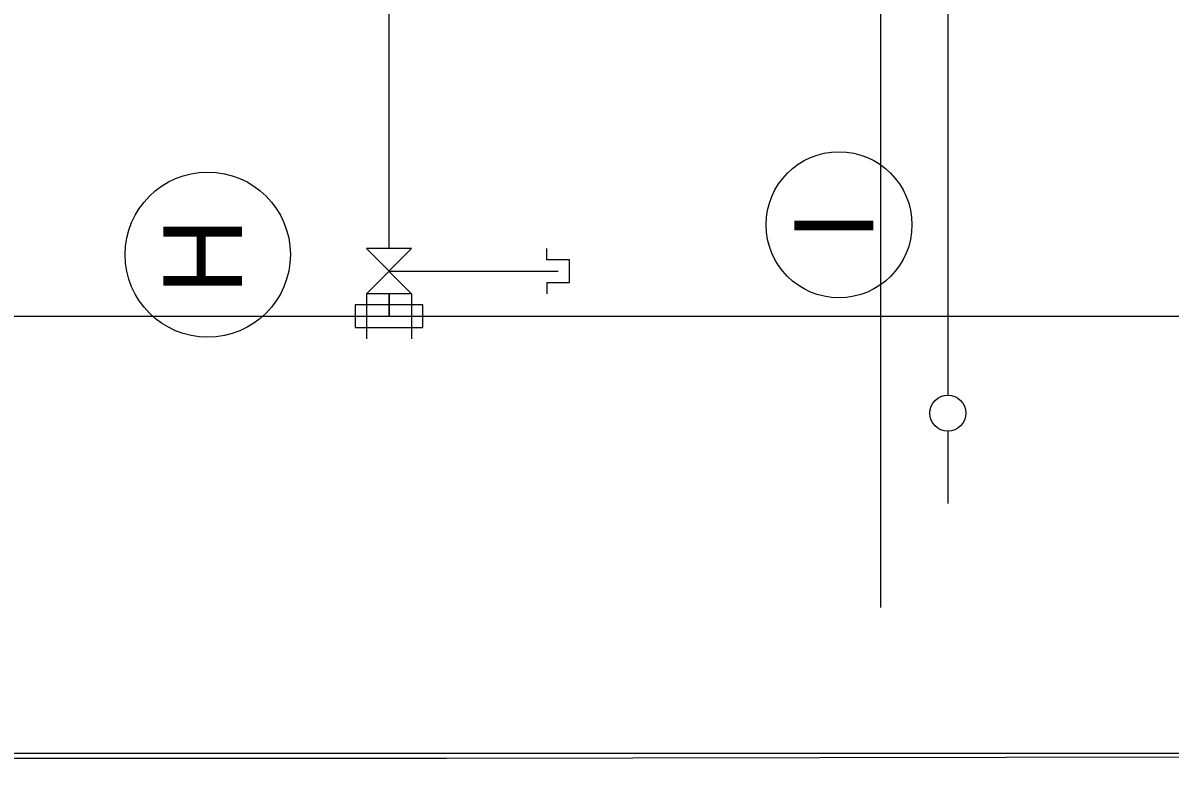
# Model space of a CAD drawing. Extents: x -264205 to -263659, y -1242401 to -1241986.
# Drawn here: x -263871.58 to -263858.86, y -1242255.16 to -1242246.89 of the extents above; entities that cross this region are included whole.
import ezdxf

# ---------------------------------------------------------------- set-up
doc = ezdxf.new("R2010")
doc.units = 0
for name, color, linetype in [('HESCON_OSI_STAVBY_KFA', 7, 'Continuous'), ('PROJEKT_OBRUBNIKY_KOMUNIKACIE', 7, 'Continuous'), ('SITUACIA_DSP_2D', 7, 'Continuous'), ('SO_20-2_OBRUBNIKY_HORNA_HRANA', 7, 'Continuous')]:
    doc.layers.add(name, color=color, linetype=linetype)

msp = doc.modelspace()

# ---------------------------------------------------------------- linework, layer by layer
at = {"layer": 'HESCON_OSI_STAVBY_KFA'}
for centre, radius in [((-263862.528, -1242249.126), 0.809), ((-263869.528, -1242249.457), 0.916)]:
    msp.add_circle(centre, radius, dxfattribs=at)
at = {"layer": 'PROJEKT_OBRUBNIKY_KOMUNIKACIE'}
msp.add_lwpolyline([(-263854.468, -1242263.985), (-263917.08, -1242263.982), (-263901.868, -1242254.982), (-263854.468, -1242254.985), (-263854.468, -1242263.985)], dxfattribs=at)
at = {"layer": 'SITUACIA_DSP_2D'}
for p, q in [((-263867.518, -1242249.39), (-263867.518, -1242235.757)), ((-263861.318, -1242235.757), (-263861.321, -1242251.015)), ((-263862.068, -1242241.132), (-263862.068, -1242253.368)), ((-263867.268, -1242249.39), (-263867.768, -1242249.39)), ((-263867.768, -1242249.89), (-263867.268, -1242249.39)), ((-263867.768, -1242249.39), (-263867.268, -1242249.89)), ((-263865.768, -1242249.515), (-263865.768, -1242249.39)), ((-263865.518, -1242249.515), (-263865.768, -1242249.515)), ((-263865.518, -1242249.765), (-263865.518, -1242249.515)), ((-263867.518, -1242249.64), (-263865.643, -1242249.64)), ((-263865.768, -1242249.765), (-263865.768, -1242249.89)), ((-263865.768, -1242249.765), (-263865.518, -1242249.765)), ((-263867.268, -1242249.89), (-263867.768, -1242249.89)), ((-263867.768, -1242249.89), (-263867.768, -1242250.39)), ((-263867.518, -1242250.14), (-263867.518, -1242249.89)), ((-263867.518, -1242249.89), (-263867.518, -1242250.14)), ((-263867.268, -1242249.89), (-263867.268, -1242250.39)), ((-263867.143, -1242250.015), (-263867.893, -1242250.015)), ((-263867.893, -1242250.015), (-263867.893, -1242250.265)), ((-263867.143, -1242250.265), (-263867.143, -1242250.015)), ((-263924.143, -1242250.14), (-263788.143, -1242250.14)), ((-263867.893, -1242250.265), (-263867.143, -1242250.265)), ((-263861.321, -1242251.415), (-263861.321, -1242252.215)), ((-263901.868, -1242254.982), (-263854.468, -1242254.985))]:
    msp.add_line(p, q, dxfattribs=at)
msp.add_circle((-263861.321, -1242251.215), 0.2, dxfattribs=at)
at = {"layer": 'SO_20-2_OBRUBNIKY_HORNA_HRANA'}
msp.add_lwpolyline([(-263854.465, -1242263.815), (-263854.458, -1242255.02), (-263866.883, -1242255.042), (-263883.752, -1242255.044), (-263902.029, -1242255.047), (-263909.175, -1242255.048), (-263919.956, -1242255.04), (-263920.002, -1242255.04)], dxfattribs=at)

# ---------------------------------------------------------------- texts
at = {"layer": 'HESCON_OSI_STAVBY_KFA'}
for s, p in [('I', (-263862.147, -1242249.296)), ('H', (-263869.147, -1242249.898))]:
    msp.add_text(s, height=0.875, rotation=90, dxfattribs=at).set_placement(p)

doc.saveas('drawing.dxf')
